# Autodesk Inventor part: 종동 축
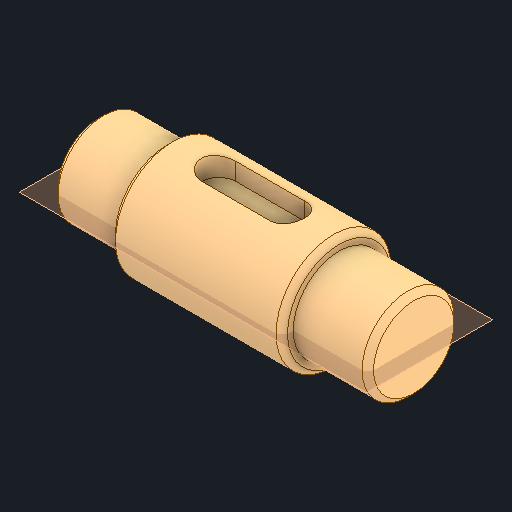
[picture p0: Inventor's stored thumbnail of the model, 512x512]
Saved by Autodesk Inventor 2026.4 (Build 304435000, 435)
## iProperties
Created: 2026-09
Part Number: 종동 축
Material: 강철, 탄소
Document SubType Name: Modeling
Designer: user
Density: 7.85 g/cm^3
Appearance: 기본값
Sending System: Autodesk Inventor 2027
Preprocessor: ST-DEVELOPER v20.1
Author: jhkim
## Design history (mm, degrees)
feature "솔리드1"
node "솔리드2"
